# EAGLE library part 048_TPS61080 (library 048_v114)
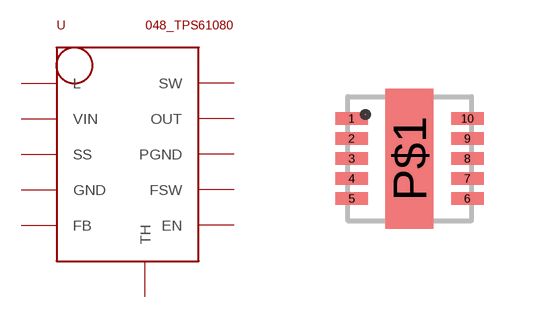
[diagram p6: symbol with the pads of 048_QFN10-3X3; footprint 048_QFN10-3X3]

Designator prefix -

## 048_TPS61080  [048_QFN10-3X3]
1  L
2  VIN
3  SS
4  GND
5  FB
6  EN
7  FSW
8  PGND
9  OUT
10  SW
P$1  TH

## Footprint 048_QFN10-3X3 (pad centres in mm)
smd 0.813 x 0.305: 1 -1.45,1; 2 -1.45,0.5; 3 -1.45,0; 4 -1.45,-0.5; 5 -1.45,-1; 6 1.45,-1; 7 1.45,-0.5; 8 1.45,0; 9 1.45,0.5; 10 1.45,1
smd 1.2 x 3.5: P$1 0,0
